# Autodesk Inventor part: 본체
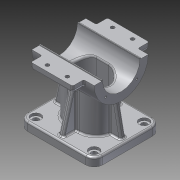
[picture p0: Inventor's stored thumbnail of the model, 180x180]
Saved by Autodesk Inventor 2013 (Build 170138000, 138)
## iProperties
Created: 2015-12
Part Number: 본체
Material: 알루미늄 6061
Document SubType Name: Modeling
Designer: mduedu
Density: 2.40731 g/cm^3
Mass: 422.298 g
Surface Area: 479.254 cm^2
Volume: 175.423 cm^3
Author: mduedu
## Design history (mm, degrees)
sketch "스케치1"
  geometry: L1 (45, 40)-(-45, 40); L2 (-45, 40)-(-45, -40); L3 (-45, -40)-(45, -40); L4 (45, -40)-(45, 40); L5 (45, 40)-(-45, -40); L6 (-45, 40)-(45, -40); 1 further point
  constraints: 12 end point, 2 midpoint, 2 parallel, 1 horizontal, 1 perpendicular
  dimensions: "d0" = 90 distance of L2.end L3.end; "d2" = 80 distance of L1.end L2.end
extrude "돌출1" new body sketch "스케치1" distance "d3" = 10; taper "d4" = 0 deg
sketch "스케치2"
  geometry: L1 (0, 40)-(0, -40) reference; C1 r 32.5 at (80, 0); 1 further point
  constraints: 1 centre point
  dimensions: "d5" = 65 diameter of C1; "d6" = 80 distance from line of C1.centre L1
extrude "돌출2" join sketch "스케치2" stored distance "d7" = 75; taper "d8" = 0 deg
sketch "스케치3"
  geometry: L1 (-27.5, -20)-(27.5, -20); L2 (27.5, -20)-(27.5, 20); L3 (27.5, 20)-(-27.5, 20); L4 (-27.5, 20)-(-27.5, -20); L5 (-27.5, -20)-(27.5, 20); L6 (27.5, -20)-(-27.5, 20); 1 further point
  constraints: 12 end point, 2 midpoint, 2 parallel, 1 horizontal, 1 perpendicular
  dimensions: "d9" = 55 distance of L2.end L3.end; "d11" = 40 distance of L1.end L2.end
extrude "돌출3" new body sketch "스케치3" stored distance "d12" = 75; taper "d13" = 0 deg
fillet "모깎기1"
fillet "모깎기2"
feature "결합1"
  node "솔리드2"
fillet "모깎기3" dims "d14" = 10
sketch "스케치4"
  geometry: L1 (-37.5, 47.5)-(37.5, 47.5) reference; L2 (35, 10)-(45, 10) reference; L3 (32.5, 47.5)-(40, 10); L4 (37.5, 47.5)-(37.5, 112.5) reference; L5 (45, 10)-(45, 0) reference; 1 further point
  constraints: 2 end point, 1 midpoint, 1 point on line
  dimensions: "d15" = 5 distance from line of L3.start L4; "d16" = 5 distance from line of L3.end L5
sketch "스케치5"
  geometry: L1 (10, 40)-(10, 30) reference; L2 (10, 35)-(56.569, 22.522); L3 (0, 40)-(10, 40) reference; 2 further points
  constraints: 2 end point, 1 midpoint, 2 other
  dimensions: "d17" = 5 distance from line of L2.start L3; "d18" = 15 deg angle of L2 L3
feature "리브1" dims "d19" = 1, "d20" = 6, "d21" = 0, "d22" = 0, "d23" = 1, "d24" = 1
feature "리브2" dims "d25" = 1, "d26" = 6, "d27" = 0, "d28" = 0, "d29" = 1, "d30" = 1
fillet "모깎기4" dims "d31" = 2
fillet "모깎기5" dims "d32" = 2
fillet "모깎기6" dims "d33" = 2
sketch "스케치6"
  geometry: A1 r 10 centre (-35, 30) between (-35, 40) and (-45, 30) reference; A2 r 10 centre (35, 30) between (45, 30) and (35, 40) reference; A3 r 10 centre (35, -30) between (35, -40) and (45, -30) reference; A4 r 10 centre (-35, -30) between (-45, -30) and (-35, -40) reference; 5 further points
  constraints: 4 coincident
hole "구멍1" sketch "스케치6" at (-35, 30), (35, 30), (35, -30), (-35, -30) diameter "d34" = 7; stored, may be unused: countersink angle "d38" = 90 deg, drill point angle "d40" = 118 deg; dims "d35" = 6, "d36" = 12, "d37" = 3, "d39" = 8
fillet "모깎기7" dims "d41" = 2
hole "구멍2" diameter "d44" = 45; stored, may be unused: countersink angle "d48" = 90 deg, drill point angle "d50" = 118 deg; dims "d42" = 10, "d43" = 10, "d45" = 6, "d46" = 4, "d47" = 2, "d49" = 8
sketch "스케치7" dims "d52" = 26.5
  geometry: L1 (0, 0)-(32.5, 0); L2 (0, 0)-(22.981, 22.981); A1 r 32.5 centre (0, 0) between (32.5, 0) and (22.981, 22.981) reference; 3 further points
  constraints: 4 end point, 2 point on circle, 1 coincident, 1 horizontal, 1 point on line, 3 other
  dimensions: "d51" = 45 deg angle of L2 L1
hole "구멍3" sketch "스케치7" at (18.738, 18.738) diameter "d54" = 2.459; stored, may be unused: countersink angle "d58" = 90 deg, drill point angle "d60" = 118 deg; dims "d55" = 8, "d56" = 4, "d57" = 2, "d59" = 10
sketch "스케치8"
  geometry: L1 (72.5, 31.623)-(72.5, 46); L2 (72.5, 46)-(87.5, 46); L3 (87.5, 46)-(87.5, 31.623); A1 r 32.5 centre (80, 0) between (87.5, 31.623) and (72.5, 31.623) reference; 2 further points
  constraints: 6 end point, 2 point on circle, 1 midpoint, 1 parallel, 1 vertical, 1 vertical alignment
  dimensions: "d64" = 15 distance of L1.end L2.end; "d66" = 46 distance from line of L2 A1.centre
extrude "돌출4" join sketch "스케치8" stored distance "d67" = 50; taper "d68" = 0 deg
fillet "모깎기8" dims "d69" = 3
fillet "모깎기9" dims "d70" = 2
sketch "스케치9"
  geometry: L1 (-76, 82.5)-(76, 82.5); L2 (76, 82.5)-(76, 0); L3 (76, 0)-(-76, 0); L4 (-76, 0)-(-76, 82.5); L5 (-46, 4.5)-(-46, -4.5) reference; C1 r 32.5 at (0, 0) reference; 2 further points
  constraints: 8 end point, 2 parallel, 1 coincident, 1 horizontal, 1 midpoint, 1 perpendicular
  dimensions: "d71" = 50 distance edge to line of C1 L1; "d72" = 30 distance between parallel lines of L4 L5
extrude "돌출5" cut sketch "스케치9" stored distance "d73" = 0; taper "d74" = 0 deg
node "작업 평면1"
sketch "스케치10"
  geometry: L1 (-7.5, 15)-(7.5, 15); L2 (-7.5, -15)-(7.5, -15); A1 r 20 centre (-7.5, 0) between (-7.5, 20) and (-26.977, 4.545) reference; A2 r 20 centre (7.5, 0) between (26.977, 4.545) and (7.5, 20) reference; A3 r 15 centre (-7.5, 0) between (-7.5, 15) and (-7.5, -15); A4 r 15 centre (7.5, 0) between (7.5, -15) and (7.5, 15); 1 further point
  constraints: 7 point on circle, 4 end point, 4 tangent, 3 point on line, 2 centre point, 2 coincident, 1 horizontal
  dimensions: "d77" = 5 radial gap between concentric circles of A3 A1
extrude "돌출6" cut sketch "스케치10" stored distance "d78" = 50; taper "d79" = 0 deg
fillet "모깎기10" dims "d80" = 3
sketch "스케치11"
  geometry: 2 further points
  constraints: 1 coincident
hole "구멍4" sketch "스케치11" at (0, 0) diameter "d81" = 12; stored, may be unused: countersink angle "d85" = 90 deg, drill point angle "d87" = 118 deg; dims "d82" = 8, "d83" = 40, "d84" = 10, "d86" = 10
sketch "스케치12"
  geometry: C1 r 10 at (0, 0); 1 further point
  constraints: 1 centre point, 1 coincident
  dimensions: "d88" = 20 diameter of C1
extrude "돌출7" cut sketch "스케치12" distance "d89" = 5; taper "d90" = 0 deg
chamfer "모따기1" distance "d91" = 1; stored, may be unused: second distance "d92" = 2, angle "d93" = 45 deg
fillet "모깎기11" dims "d94" = 0.5
feature "립1" dims "d95" = 1, "d96" = 1, "d97" = 0, "d98" = 3 deg, "d99" = 3 deg, "d100" = 0
sketch "스케치13"
  geometry: 4 further points
hole "구멍5" sketch "스케치13" at (34, 5.936), (10, -72.269), (34, -72.269), (10, 5.936) diameter "d101" = 4.5; stored, may be unused: countersink angle "d105" = 90 deg, drill point angle "d107" = 0 deg; dims "d102" = 6, "d103" = 4, "d104" = 2, "d106" = 8
fillet "모깎기12" dims "d115" = 0.3
node "솔리드1"
mirror "대칭1"
mirror "대칭2"
pattern_circular "원형 패턴1" dims angle "d62" = 360 deg
mirror "대칭3"
mirror "대칭4"
